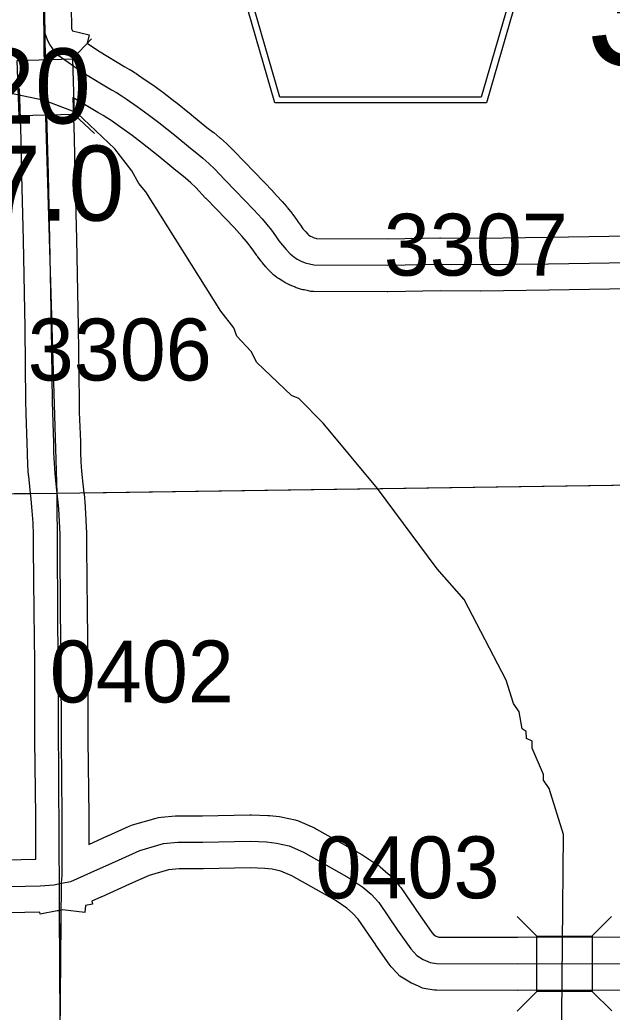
# Model space of a CAD drawing. Extents: x 23.6 to 68.7, y -63 to -29.
# Drawn here: x 40.707 to 41.377, y -52.217 to -51.095 of the extents above; entities that cross this region are included whole.
import ezdxf

# ---------------------------------------------------------------- set-up
doc = ezdxf.new("R2010")
doc.units = 0
for name, color, linetype in [('tdCoHydroRiver', 7, 'Continuous'), ('tdCoSecRdNmbr', 7, 'Continuous'), ('tdCoSecRteBand', 7, 'Continuous'), ('tdCoSecRteCL', 7, 'Continuous'), ('tdCoSectLine', 7, 'Continuous'), ('tdCoSectLinePart', 7, 'Continuous'), ('tdCoSectNmbr', 7, 'Continuous'), ('tdCoShieldCoRteHrd', 7, 'Continuous'), ('tdCoStrucSec', 7, 'Continuous'), ('tdCoStrucSecCoName', 7, 'Continuous'), ('tdCoStrucSecFHWANum', 7, 'Continuous'), ('tdCoSurfGravel', 7, 'Continuous'), ('tdCoSurfLNO', 7, 'Continuous'), ('tdCoTwpBndry', 7, 'Continuous'), ('tdCoTwpBndryShd', 7, 'Continuous')]:
    doc.layers.add(name, color=color, linetype=linetype)

msp = doc.modelspace()

# ---------------------------------------------------------------- linework, layer by layer
at = {"layer": 'tdCoHydroRiver'}
for points in [[(41.0502, -51.5508), (41.0225, -51.5226), (41.0144, -51.5195), (40.9753, -51.4819), (40.9686, -51.4694), (40.9523, -51.4521), (40.9489, -51.4427), (40.9345, -51.4239), (40.8496, -51.2889), (40.8416, -51.2795), (40.8336, -51.2654), (40.8144, -51.2403), (40.7714, -51.1997), (40.735, -51.1858), (40.5325, -51.1435), (40.3872, -51.1323), (40.3256, -51.1281)], [(41.3198, -52.262), (41.3222, -52.0157), (41.3059, -51.9637), (41.2995, -51.9543), (41.2994, -51.948), (41.2865, -51.9182), (41.2865, -51.9103), (41.2801, -51.9072), (41.28, -51.8993), (41.2753, -51.8962), (41.2719, -51.8772), (41.2655, -51.8678), (41.2572, -51.8411), (41.2099, -51.7499), (41.1793, -51.7154), (41.1115, -51.6245), (41.0502, -51.5508)]]:
    msp.add_lwpolyline(points, dxfattribs=at)
at = {"layer": 'tdCoSecRteBand'}
for points in [[(40.7651, -51.0795), (40.7655, -51.1045), (40.7659, -51.1055), (40.7666, -51.1068), (40.7855, -51.1116), (40.7832, -51.1208), (40.7958, -51.1295), (40.8258, -51.1477), (40.8309, -51.1506), (40.8315, -51.1509), (40.8321, -51.1512), (40.8375, -51.1546), (40.8381, -51.155), (40.8386, -51.1553), (40.8439, -51.1589), (40.844, -51.159), (40.844, -51.159), (40.8566, -51.1676), (40.857, -51.1679), (40.8573, -51.1681), (40.8697, -51.1771), (40.87, -51.1773), (40.8703, -51.1776), (40.8825, -51.1869), (40.8827, -51.1871), (40.883, -51.1873), (40.9009, -51.2017), (40.901, -51.2018), (40.9011, -51.2018), (40.9187, -51.2162), (40.9256, -51.2215), (40.926, -51.2218), (40.9264, -51.2221), (40.9333, -51.2279), (40.9337, -51.2282), (40.934, -51.2285), (40.9408, -51.2345), (40.9411, -51.2349), (40.9415, -51.2352), (40.948, -51.2414), (40.9486, -51.242), (40.9492, -51.2426), (40.9607, -51.2548), (40.9724, -51.2668), (40.9725, -51.2668), (40.9725, -51.2668), (40.9827, -51.2773), (40.9829, -51.2775), (40.983, -51.2777), (40.9931, -51.2883), (40.9933, -51.2885), (40.9934, -51.2887), (41.0033, -51.2995), (41.0035, -51.2997), (41.0036, -51.2999), (41.0091, -51.3061), (41.0095, -51.3066), (41.01, -51.3072), (41.0151, -51.3136), (41.0155, -51.3142), (41.016, -51.3148), (41.0208, -51.3214), (41.021, -51.3218), (41.0213, -51.3222), (41.0244, -51.3268), (41.0273, -51.3307), (41.0305, -51.3343), (41.0329, -51.3369), (41.0341, -51.3379), (41.0359, -51.3391), (41.0379, -51.3401), (41.0399, -51.3409), (41.042, -51.3415), (41.0426, -51.3417), (41.1226, -51.3421)], [(40.5768, -52.0472), (40.725, -52.0438), (40.725, -51.9948), (40.724, -51.9092), (40.724, -51.909), (40.724, -51.9089), (40.7238, -51.8213), (40.723, -51.7638), (40.723, -51.7637), (40.723, -51.7635), (40.7225, -51.6907), (40.7224, -51.6769), (40.7219, -51.6634), (40.721, -51.6499), (40.7199, -51.6364), (40.7191, -51.6297), (40.7183, -51.6226), (40.7182, -51.6224), (40.7182, -51.6222), (40.717, -51.6106), (40.717, -51.6102), (40.7169, -51.6097), (40.7161, -51.5981), (40.7161, -51.5976), (40.716, -51.5972), (40.7156, -51.5855), (40.7155, -51.5851), (40.7155, -51.5846), (40.7154, -51.5734), (40.7141, -51.5399), (40.7141, -51.5395), (40.7141, -51.5391), (40.7139, -51.526), (40.7128, -51.4427), (40.711, -51.3437), (40.7093, -51.2702), (40.7084, -51.2297), (40.7067, -51.1721)], [(41.4199, -51.3985), (41.3058, -51.4003), (41.3057, -51.4003), (41.3057, -51.4003), (41.2287, -51.4013), (41.2284, -51.4013), (41.2281, -51.4013), (41.1828, -51.401), (41.1234, -51.4021), (41.123, -51.4021), (41.1226, -51.4021), (41.0393, -51.4016), (41.0363, -51.4016), (41.0334, -51.401), (41.0285, -51.4), (41.0272, -51.3998), (41.0258, -51.3993), (41.0211, -51.3979), (41.0197, -51.3975), (41.0184, -51.3969), (41.0138, -51.395), (41.0125, -51.3945), (41.0112, -51.3939), (41.0068, -51.3915), (41.0056, -51.3909), (41.0044, -51.3901), (41.0002, -51.3874), (40.999, -51.3866), (40.9979, -51.3858), (40.994, -51.3827), (40.9924, -51.3814), (40.991, -51.3799), (40.9865, -51.3752), (40.9859, -51.3746), (40.9853, -51.3739), (40.9811, -51.369), (40.9806, -51.3683), (40.9801, -51.3676), (40.9761, -51.3625), (40.9756, -51.3618), (40.9752, -51.3611), (40.9718, -51.3561), (40.9677, -51.3504), (40.9635, -51.3451), (40.9587, -51.3397), (40.9493, -51.3293), (40.9396, -51.319), (40.9296, -51.3088), (40.9176, -51.2966), (40.9174, -51.2964), (40.9172, -51.2961), (40.906, -51.2843), (40.9005, -51.279), (40.8945, -51.2737), (40.8883, -51.2685), (40.8816, -51.2633), (40.8814, -51.2631), (40.8811, -51.2629), (40.8633, -51.2484), (40.8457, -51.2343), (40.8341, -51.2254), (40.8224, -51.2169), (40.8101, -51.2085), (40.8054, -51.2053), (40.8011, -51.2026), (40.7961, -51.1998), (40.7956, -51.1996), (40.7952, -51.1993), (40.767, -51.1822), (40.7683, -51.228), (40.7683, -51.2281), (40.7683, -51.2281), (40.7693, -51.2687), (40.7693, -51.2688), (40.7693, -51.2688), (40.771, -51.3425), (40.771, -51.3425), (40.771, -51.3426), (40.7728, -51.4417), (40.7728, -51.4418), (40.7728, -51.4418), (40.7739, -51.5252), (40.7739, -51.5252), (40.7739, -51.5252), (40.7741, -51.538), (40.7754, -51.5715), (40.7754, -51.5719), (40.7754, -51.5723), (40.7755, -51.5835), (40.776, -51.5942), (40.7767, -51.6049), (40.7779, -51.6159), (40.7787, -51.6228), (40.7795, -51.6299), (40.7795, -51.6303), (40.7796, -51.6307), (40.7808, -51.645), (40.7809, -51.6454), (40.7809, -51.6458), (40.7818, -51.66), (40.7818, -51.6604), (40.7818, -51.6608), (40.7823, -51.6751), (40.7824, -51.6755), (40.7824, -51.6759), (40.7825, -51.6902), (40.7825, -51.6903), (40.7825, -51.6903), (40.783, -51.763), (40.7838, -51.8206), (40.7838, -51.8208), (40.7838, -51.821), (40.784, -51.9086), (40.785, -51.9943), (40.785, -51.9945), (40.785, -51.9947), (40.785, -52.0271), (40.8063, -52.0173), (40.8064, -52.0173), (40.8065, -52.0172), (40.8306, -52.0064), (40.8326, -52.0055), (40.8346, -52.0049), (40.8613, -51.9973), (40.864, -51.9965), (40.8668, -51.9962), (40.8831, -51.9947), (40.8845, -51.9946), (40.8858, -51.9946), (40.9136, -51.9946), (40.9673, -51.9934), (40.9682, -51.9934), (40.9692, -51.9934), (40.9874, -51.9942), (40.9884, -51.9942), (40.9894, -51.9943), (41.0008, -51.9955), (41.0025, -51.9957), (41.0041, -51.9961), (41.0184, -51.9993), (41.0212, -51.9999), (41.0239, -52.0011), (41.0402, -52.0083), (41.0415, -52.0088), (41.0428, -52.0096), (41.0941, -52.0384), (41.0952, -52.039), (41.0961, -52.0397), (41.1119, -52.0503), (41.1134, -52.0513), (41.1148, -52.0525), (41.1239, -52.0604), (41.1252, -52.0615), (41.1264, -52.0627), (41.1352, -52.0723), (41.1367, -52.074), (41.138, -52.0758), (41.1591, -52.1067), (41.173, -52.1265), (41.1754, -52.1292), (41.1774, -52.1304), (41.1799, -52.1316), (41.1811, -52.1317), (41.2703, -52.132)], [(41.1226, -51.3421), (41.1821, -51.341), (41.1825, -51.341), (41.1829, -51.341), (41.2283, -51.3413), (41.3049, -51.3403), (41.4193, -51.3385)], [(41.534, -52.1915), (41.2703, -52.192), (41.2703, -52.192), (41.2702, -52.192), (41.1785, -52.1917), (41.176, -52.1917), (41.1736, -52.1913), (41.1662, -52.1901), (41.1624, -52.1895), (41.1588, -52.1878), (41.1512, -52.1844), (41.1496, -52.1837), (41.1481, -52.1828), (41.1407, -52.1783), (41.1368, -52.176), (41.1338, -52.1727), (41.1272, -52.1653), (41.1259, -52.1639), (41.1249, -52.1624), (41.1098, -52.141), (41.1097, -52.1408), (41.1096, -52.1407), (41.0897, -52.1114), (41.0834, -52.1047), (41.077, -52.0991), (41.0637, -52.0901), (41.0147, -52.0626), (41.0024, -52.0572), (40.9926, -52.055), (40.984, -52.0541), (40.9677, -52.0534), (40.9146, -52.0546), (40.9143, -52.0546), (40.9139, -52.0546), (40.8872, -52.0546), (40.8751, -52.0557), (40.8533, -52.062), (40.8311, -52.0719), (40.7999, -52.0862), (40.7996, -52.0863), (40.7994, -52.0864), (40.7884, -52.0912), (40.789, -52.0947), (40.7814, -52.0961), (40.7805, -52.1039), (40.7552, -52.1011), (40.7509, -52.1019), (40.7493, -52.1022), (40.7493, -52.1022), (40.7301, -52.1059), (40.7297, -52.1037), (40.578, -52.1071)], [(41.2703, -52.132), (41.5335, -52.1315)]]:
    msp.add_lwpolyline(points, dxfattribs=at)
at = {"layer": 'tdCoSecRteCL'}
msp.add_line((40.7361, -51.1416), (40.7355, -51.11), dxfattribs=at)
for points in [[(40.7355, -51.11), (40.7349, -51.07), (40.7346, -51.0268), (40.7326, -50.93), (40.7313, -50.8419), (40.7308, -50.8195), (40.7307, -50.7924)], [(40.7491, -51.1333), (40.7461, -51.1299), (40.7434, -51.1263), (40.7409, -51.1225), (40.7388, -51.1184), (40.737, -51.1143), (40.7355, -51.11)], [(40.7361, -51.1416), (40.7364, -51.1396), (40.7372, -51.1378), (40.7383, -51.1362), (40.7397, -51.1348), (40.7414, -51.1338), (40.7432, -51.1331), (40.7452, -51.1328), (40.7471, -51.1328), (40.7491, -51.1333)], [(40.7491, -51.1333), (40.7502, -51.1345), (40.7795, -51.1547), (40.8107, -51.1736), (40.8163, -51.1768), (40.8217, -51.1801), (40.8271, -51.1837), (40.8397, -51.1924), (40.8521, -51.2014), (40.8642, -51.2107), (40.8822, -51.2251), (40.9, -51.2396), (40.9072, -51.2452), (40.9141, -51.2509), (40.9208, -51.2569), (40.9273, -51.2631), (40.939, -51.2756), (40.951, -51.2878), (40.9612, -51.2983), (40.9713, -51.3089), (40.9811, -51.3197), (40.9865, -51.3259), (40.9916, -51.3323), (40.9964, -51.3389), (41, -51.3443), (41.004, -51.3495), (41.0082, -51.3544), (41.0127, -51.3592), (41.0166, -51.3623), (41.0208, -51.365), (41.0252, -51.3673), (41.0298, -51.3692), (41.0346, -51.3706), (41.0395, -51.3716), (41.1228, -51.3721), (41.1827, -51.371), (41.2284, -51.3713), (41.3053, -51.3703), (41.4197, -51.3685)], [(40.754, -52.0708), (40.755, -52.0616), (40.755, -51.9947), (40.754, -51.9088), (40.7538, -51.821), (40.753, -51.7633), (40.7525, -51.6905), (40.7524, -51.6762), (40.7519, -51.6619), (40.751, -51.6476), (40.7497, -51.6334), (40.7489, -51.6263), (40.7481, -51.6192), (40.7469, -51.6076), (40.746, -51.5959), (40.7455, -51.5843), (40.7454, -51.5726), (40.7441, -51.5388), (40.7439, -51.5256), (40.7428, -51.4423), (40.741, -51.3431), (40.7393, -51.2695), (40.7384, -51.2289), (40.7364, -51.1615), (40.7361, -51.1416)], [(40.754, -52.0708), (40.7647, -52.0688), (40.7874, -52.0589), (40.8187, -52.0446), (40.8429, -52.0337), (40.8696, -52.0261), (40.8858, -52.0246), (40.9139, -52.0246), (40.9679, -52.0234), (40.9862, -52.0241), (40.9975, -52.0254), (41.0118, -52.0286), (41.0281, -52.0357), (41.0794, -52.0646), (41.0952, -52.0752), (41.1043, -52.0831), (41.1132, -52.0927), (41.1344, -52.1238), (41.1494, -52.1452), (41.1561, -52.1526), (41.1635, -52.1571), (41.1712, -52.1605), (41.1785, -52.1617), (41.2703, -52.162), (41.5339, -52.1615)], [(40.5773, -52.0772), (40.73, -52.0737), (40.7453, -52.0725), (40.754, -52.0708)]]:
    msp.add_lwpolyline(points, dxfattribs=at)
at = {"layer": 'tdCoSectLine'}
for points in [[(40.7288, -50.6241), (40.7345, -51.1539), (40.7489, -51.6298)], [(40.7489, -51.6298), (41.7431, -51.6156)], [(39.7356, -51.6376), (40.7489, -51.6298)], [(40.7489, -51.6298), (40.7549, -52.667)]]:
    msp.add_lwpolyline(points, dxfattribs=at)
at = {"layer": 'tdCoSectLinePart'}
for points in [[(40.779, -51.6294), (41.7431, -51.6156)], [(39.7656, -51.6373), (40.7188, -51.63)], [(40.7516, -52.1015), (40.7549, -52.667)]]:
    msp.add_lwpolyline(points, dxfattribs=at)
at = {"layer": 'tdCoShieldCoRteHrd'}
for points in [[(40.9954, -51.1884), (40.9135, -50.9055), (40.9096, -50.8923), (40.9089, -50.8864), (40.9089, -50.8786), (40.9131, -50.8683), (40.9204, -50.8598), (40.93, -50.8532), (41.0972, -50.7808), (41.1047, -50.7792), (41.1152, -50.7783), (41.1256, -50.7792), (41.1331, -50.7808), (41.3004, -50.8532), (41.31, -50.8598), (41.3172, -50.8683), (41.3215, -50.8786), (41.3215, -50.8864), (41.3208, -50.8923), (41.3169, -50.9055), (41.2349, -51.1884)], [(41.0013, -51.182), (40.9215, -50.9068), (40.9178, -50.8941), (40.9171, -50.8885), (40.9171, -50.881), (40.9212, -50.8711), (40.9282, -50.8629), (40.9374, -50.8565), (41.0979, -50.7871), (41.1052, -50.7855), (41.1152, -50.7846), (41.1252, -50.7855), (41.1324, -50.7871), (41.293, -50.8565), (41.3022, -50.8629), (41.3092, -50.8711), (41.3132, -50.881), (41.3132, -50.8885), (41.3125, -50.8941), (41.3088, -50.9068), (41.2291, -51.182)]]:
    msp.add_lwpolyline(points, close=True, dxfattribs=at)
at = {"layer": 'tdCoStrucSec'}
for p, q in [((40.7667, -51.1388), (40.7882, -51.1161)), ((40.7685, -51.2014), (40.7913, -51.2229)), ((41.2918, -52.1306), (41.2696, -52.1085)), ((41.3544, -52.1305), (41.3765, -52.1083)), ((41.2919, -52.1932), (41.2698, -52.2154)), ((41.3545, -52.1931), (41.3767, -52.2152))]:
    msp.add_line(p, q, dxfattribs=at)
for points in [[(40.706, -51.2032), (40.7041, -51.1407), (40.7667, -51.1388), (40.7685, -51.2014)], [(41.2918, -52.1306), (41.3544, -52.1305), (41.3545, -52.1931), (41.2919, -52.1932)]]:
    msp.add_lwpolyline(points, close=True, dxfattribs=at)
at = {"layer": 'tdCoSurfGravel'}
for points in [[(40.7489, -51.6263), (40.7481, -51.6192), (40.7469, -51.6076), (40.746, -51.5959), (40.7455, -51.5843), (40.7454, -51.5726), (40.7441, -51.5388), (40.7439, -51.5256), (40.7428, -51.4423), (40.741, -51.3431), (40.7393, -51.2695), (40.7384, -51.2289), (40.7364, -51.1615), (40.7361, -51.1416), (40.7355, -51.11), (40.7349, -51.07)], [(40.7491, -51.1333), (40.7461, -51.1299), (40.7434, -51.1263), (40.7409, -51.1225), (40.7388, -51.1184), (40.737, -51.1143), (40.7355, -51.11)], [(40.7361, -51.1416), (40.7364, -51.1396), (40.7372, -51.1378), (40.7383, -51.1362), (40.7397, -51.1348), (40.7414, -51.1338), (40.7432, -51.1331), (40.7452, -51.1328), (40.7471, -51.1328), (40.7491, -51.1333), (40.7502, -51.1345), (40.7795, -51.1547), (40.8107, -51.1736), (40.8163, -51.1768), (40.8217, -51.1801), (40.8271, -51.1837), (40.8397, -51.1924), (40.8521, -51.2014), (40.8642, -51.2107), (40.8822, -51.2251), (40.9, -51.2396), (40.9072, -51.2452), (40.9141, -51.2509), (40.9208, -51.2569), (40.9273, -51.2631), (40.939, -51.2756), (40.951, -51.2878), (40.9612, -51.2983), (40.9713, -51.3089), (40.9811, -51.3197), (40.9865, -51.3259), (40.9916, -51.3323), (40.9964, -51.3389), (41, -51.3443), (41.004, -51.3495), (41.0082, -51.3544), (41.0127, -51.3592), (41.0166, -51.3623), (41.0208, -51.365), (41.0252, -51.3673), (41.0298, -51.3692), (41.0346, -51.3706), (41.0395, -51.3716), (41.1228, -51.3721), (41.1827, -51.371), (41.2284, -51.3713), (41.3053, -51.3703), (41.4197, -51.3685)], [(40.754, -52.0708), (40.755, -52.0616), (40.755, -51.9947), (40.754, -51.9088), (40.7538, -51.821), (40.753, -51.7633), (40.7525, -51.6905), (40.7524, -51.6762), (40.7519, -51.6619), (40.751, -51.6476), (40.7497, -51.6334), (40.7489, -51.6263)], [(40.5773, -52.0772), (40.73, -52.0737), (40.7453, -52.0725), (40.754, -52.0708), (40.7647, -52.0688), (40.7874, -52.0589), (40.8187, -52.0446), (40.8429, -52.0337), (40.8696, -52.0261), (40.8858, -52.0246), (40.9139, -52.0246), (40.9679, -52.0234), (40.9862, -52.0241), (40.9975, -52.0254), (41.0118, -52.0286), (41.0281, -52.0357), (41.0794, -52.0646), (41.0952, -52.0752), (41.1043, -52.0831), (41.1132, -52.0927), (41.1344, -52.1238), (41.1494, -52.1452), (41.1561, -52.1526), (41.1635, -52.1571), (41.1712, -52.1605), (41.1785, -52.1617), (41.2703, -52.162), (41.5339, -52.1615)]]:
    msp.add_lwpolyline(points, dxfattribs=at)
at = {"layer": 'tdCoSurfLNO'}
msp.add_line((40.7513, -52.3731), (40.754, -52.0708), dxfattribs=at)
at = {"layer": 'tdCoTwpBndry'}
for points in [[(40.7791, -51.6294), (41.7431, -51.6156), (42.2048, -51.6063)], [(39.7657, -51.6373), (40.7188, -51.63)]]:
    msp.add_lwpolyline(points, dxfattribs=at)
at = {"layer": 'tdCoTwpBndryShd'}
msp.add_lwpolyline([(39.7356, -51.6376), (40.7489, -51.6298), (41.7431, -51.6156), (42.7527, -51.5953), (43.7365, -51.5949), (44.7293, -51.5796), (45.7019, -51.569), (46.6986, -51.5546)], dxfattribs=at)

# ---------------------------------------------------------------- texts
at = {"layer": 'tdCoSecRdNmbr'}
for s, rotation, p in [('3307', 0.0322, (41.1188, -51.3838)), ('3306', 0.0319, (40.7159, -51.5024)), ('0402', 0.0319, (40.7409, -51.8665)), ('0403', 0.0321, (41.0415, -52.088))]:
    msp.add_text(s, height=0.07, rotation=rotation, dxfattribs=at).set_placement(p)
at = {"layer": 'tdCoSectNmbr'}
msp.add_text('33', height=0.13, rotation=1.0323, dxfattribs=at).set_placement((41.3484, -51.1467))
at = {"layer": 'tdCoStrucSecCoName'}
msp.add_text('GF322627.0', height=0.085, dxfattribs=at).set_placement((40.1933, -51.3217))
at = {"layer": 'tdCoStrucSecFHWANum'}
msp.add_text('236620', height=0.085, dxfattribs=at).set_placement((40.408, -51.2118))

doc.saveas('drawing.dxf')
